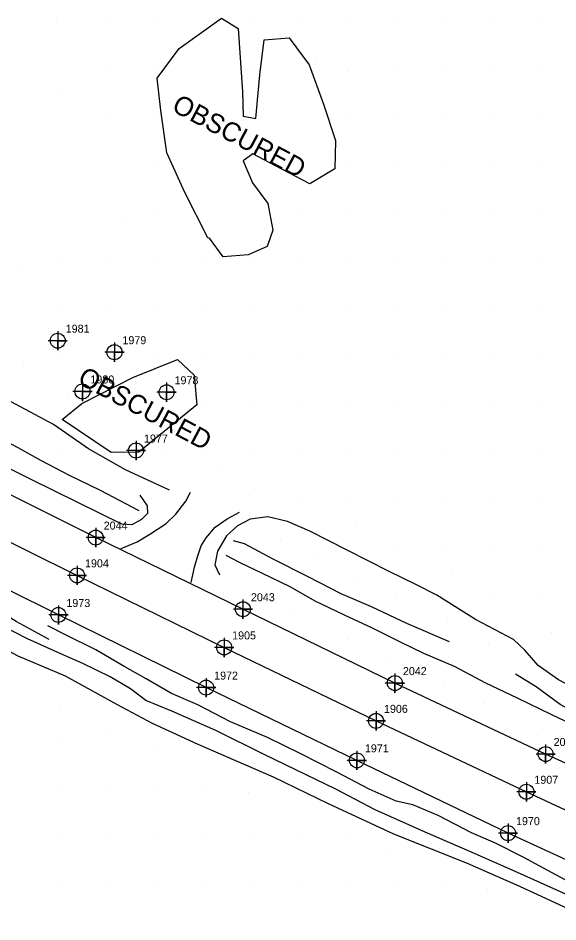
# Model space of a CAD drawing. Extents: x 1497074 to 1501343, y 481943 to 486114.
# Drawn here: x 1499522.1 to 1499690.7, y 482804.6 to 483087 of the extents above; entities that cross this region are included whole.
import ezdxf

# ---------------------------------------------------------------- set-up
doc = ezdxf.new("R2010")
doc.units = 0
for name, color, linetype in [('Exist DTM Crownline', 7, 'Continuous'), ('Exist DTM Crownline Cogo Number', 7, 'Continuous'), ('Exist DTM Crownline Cogo Point CELL', 7, 'Continuous'), ('Exist DTM Regular Point CELL', 7, 'Continuous'), ('Exist DTM Regular Point Cogo Number', 7, 'Continuous'), ('Exist Roads EOP', 7, 'Continuous'), ('Exist Roads EOP Cogo Number', 7, 'Continuous'), ('Exist Roads EOP Cogo Point CELL', 7, 'Continuous'), ('PH Exist DTM Breakline', 7, 'Continuous'), ('PH Exist DTM Obscure Area', 7, 'Continuous'), ('PH Exist DTM Obscure Area Text', 7, 'Continuous'), ('PH Exist DTM Point', 7, 'Continuous')]:
    doc.layers.add(name, color=color, linetype=linetype)

msp = doc.modelspace()

# ---------------------------------------------------------------- linework, layer by layer
at = {"layer": 'Exist DTM Crownline'}
msp.add_lwpolyline([(1499395.36, 482985.02), (1499443.87, 482960.81), (1499493.08, 482936.36), (1499540.5, 482912.88), (1499586.46, 482890.36), (1499633.9, 482867.4), (1499680.88, 482845.25), (1499726.12, 482824.18), (1499773.19, 482803.77), (1499819.04, 482785.34), (1499906.6, 482751.56), (1499930.69, 482742.84), (1499979.87, 482724.77), (1500026.26, 482708.17), (1500077.15, 482689.67), (1500127.52, 482671.55), (1500177.68, 482653.78), (1500231.5, 482634.52), (1500279.65, 482617.19), (1500328.73, 482599.71), (1500369.66, 482584.94)], dxfattribs=at)
at = {"layer": 'Exist DTM Crownline Cogo Point CELL'}
for points in [[(1499540.5, 482915.88), (1499540.5, 482909.88), (1499540.5, 482912.88), (1499543.5, 482912.88), (1499537.5, 482912.88)], [(1499586.46, 482893.36), (1499586.46, 482887.36), (1499586.46, 482890.36), (1499589.46, 482890.36), (1499583.46, 482890.36)], [(1499633.9, 482870.4), (1499633.9, 482864.4), (1499633.9, 482867.4), (1499636.9, 482867.4), (1499630.9, 482867.4)], [(1499680.88, 482848.25), (1499680.88, 482842.25), (1499680.88, 482845.25), (1499683.88, 482845.25), (1499677.88, 482845.25)]]:
    msp.add_lwpolyline(points, dxfattribs=at)
for centre in [(1499540.5, 482912.88), (1499586.46, 482890.36), (1499633.9, 482867.4), (1499680.88, 482845.25)]:
    msp.add_circle(centre, 2.34, dxfattribs=at)
at = {"layer": 'Exist DTM Regular Point CELL'}
for points in [[(1499534.46, 482989.2), (1499534.46, 482983.2), (1499534.46, 482986.2), (1499537.46, 482986.2), (1499531.46, 482986.2)], [(1499552.19, 482985.6), (1499552.19, 482979.6), (1499552.19, 482982.6), (1499555.19, 482982.6), (1499549.19, 482982.6)], [(1499542.19, 482973.34), (1499542.19, 482967.34), (1499542.19, 482970.34), (1499545.19, 482970.34), (1499539.19, 482970.34)], [(1499568.47, 482973.09), (1499568.47, 482967.09), (1499568.47, 482970.09), (1499571.47, 482970.09), (1499565.47, 482970.09)], [(1499558.92, 482954.88), (1499558.92, 482948.88), (1499558.92, 482951.88), (1499561.92, 482951.88), (1499555.92, 482951.88)]]:
    msp.add_lwpolyline(points, dxfattribs=at)
for centre in [(1499534.46, 482986.2), (1499552.19, 482982.6), (1499542.19, 482970.34), (1499568.47, 482970.09), (1499558.92, 482951.88)]:
    msp.add_circle(centre, 2.34, dxfattribs=at)
at = {"layer": 'Exist Roads EOP'}
for points in [[(1499731.6, 482836.87), (1499686.89, 482857.05), (1499639.8, 482879.21), (1499592.33, 482902.29), (1499546.33, 482924.68), (1499498.59, 482948.51), (1499459.31, 482968.94), (1499458.43, 482969.66), (1499428.27, 482984.38), (1499427.08, 482984.62), (1499402.41, 482996.96)], [(1499698.51, 482821.61), (1499675.14, 482832.32), (1499627.94, 482855.07), (1499580.83, 482877.79), (1499534.68, 482900.49), (1499486.84, 482924.26), (1499438.05, 482948.62), (1499388.86, 482973.08)]]:
    msp.add_lwpolyline(points, dxfattribs=at)
at = {"layer": 'Exist Roads EOP Cogo Point CELL'}
for points in [[(1499546.33, 482927.68), (1499546.33, 482921.68), (1499546.33, 482924.68), (1499549.33, 482924.68), (1499543.33, 482924.68)], [(1499592.33, 482905.29), (1499592.33, 482899.29), (1499592.33, 482902.29), (1499595.33, 482902.29), (1499589.33, 482902.29)], [(1499534.68, 482903.49), (1499534.68, 482897.49), (1499534.68, 482900.49), (1499537.68, 482900.49), (1499531.68, 482900.49)], [(1499639.8, 482882.21), (1499639.8, 482876.21), (1499639.8, 482879.21), (1499642.8, 482879.21), (1499636.8, 482879.21)], [(1499580.83, 482880.79), (1499580.83, 482874.79), (1499580.83, 482877.79), (1499583.83, 482877.79), (1499577.83, 482877.79)], [(1499686.89, 482860.05), (1499686.89, 482854.05), (1499686.89, 482857.05), (1499689.89, 482857.05), (1499683.89, 482857.05)], [(1499627.94, 482858.07), (1499627.94, 482852.07), (1499627.94, 482855.07), (1499630.94, 482855.07), (1499624.94, 482855.07)], [(1499675.14, 482835.32), (1499675.14, 482829.32), (1499675.14, 482832.32), (1499678.14, 482832.32), (1499672.14, 482832.32)]]:
    msp.add_lwpolyline(points, dxfattribs=at)
for centre in [(1499546.33, 482924.68), (1499592.33, 482902.29), (1499534.68, 482900.49), (1499639.8, 482879.21), (1499580.83, 482877.79), (1499686.89, 482857.05), (1499627.94, 482855.07), (1499675.14, 482832.32)]:
    msp.add_circle(centre, 2.34, dxfattribs=at)
at = {"layer": 'PH Exist DTM Breakline'}
for points in [[(1499569.38, 482939.45), (1499555.59, 482945.83), (1499544.06, 482952.45), (1499533.12, 482960.03), (1499519.92, 482967.05), (1499506.63, 482974.11), (1499495.82, 482979.85), (1499485.92, 482984.72), (1499476.91, 482989.41), (1499465.54, 482994.89)], [(1499554.47, 482928.86), (1499526.35, 482942.7), (1499499.25, 482956.26), (1499476.52, 482967.92), (1499464.94, 482974.18), (1499461.69, 482976.81), (1499460.19, 482979.45), (1499460.13, 482984.35), (1499460.87, 482990.61)], [(1499531.84, 482892.85), (1499521.45, 482898.49), (1499512.58, 482903.98), (1499499.86, 482910.46), (1499487.99, 482916.64), (1499479.25, 482921.85), (1499471.5, 482925.48), (1499460.32, 482930.95), (1499448.67, 482936.16), (1499435.81, 482941.98), (1499423.89, 482948.31), (1499412.5, 482953.79), (1499400.01, 482960.42), (1499390.51, 482965.44), (1499382.74, 482969.27), (1499372.58, 482974.7), (1499364.12, 482978.83), (1499355.7, 482982.98), (1499348.93, 482986.12)], [(1499559.95, 482933), (1499547.84, 482939.44), (1499538.16, 482944.09), (1499529.39, 482948.65), (1499522.08, 482952.68), (1499514.27, 482956.74), (1499507.24, 482960.1), (1499499.29, 482963.79), (1499490.71, 482967.25), (1499483.35, 482970.57), (1499475.46, 482974.49), (1499462.75, 482980.59)], [(1499339.96, 482972.14), (1499355.23, 482965.11), (1499369.9, 482958.45), (1499380.09, 482953.58), (1499393.87, 482947.39), (1499408.71, 482939.89), (1499424.74, 482932.88), (1499443.1, 482924.02), (1499461.53, 482915.83), (1499479.74, 482907.55), (1499491.77, 482902.64), (1499508.84, 482894.62), (1499522.01, 482887.72), (1499536.81, 482881.48), (1499553, 482872.55), (1499563.99, 482866.65), (1499578.21, 482860.08), (1499601.81, 482849.91), (1499618.96, 482841.56), (1499639.41, 482832.09), (1499662.39, 482822.9), (1499678.74, 482815.76), (1499696.7, 482807.4)], [(1499554.26, 482921.29), (1499559.29, 482923.4), (1499563.27, 482925.75), (1499568.35, 482929.05), (1499571.36, 482931.96), (1499574.49, 482936.07), (1499575.98, 482938.87)], [(1499560.15, 482937.92), (1499562.37, 482934.58), (1499562.51, 482932.17), (1499560.66, 482930.28), (1499557.63, 482928.61), (1499554.47, 482928.86)], [(1499576.18, 482910.69), (1499577.24, 482915.48), (1499578.1, 482918.67), (1499579.3, 482922.15), (1499580.87, 482924.6), (1499583.68, 482927.89), (1499587.37, 482930.55), (1499591.29, 482932.58)], [(1499728.17, 482864.71), (1499702.51, 482874.12), (1499690.89, 482880.26), (1499684.61, 482884.66), (1499680.37, 482889.51), (1499676.82, 482892.78), (1499664.97, 482899.08), (1499652.87, 482906.64), (1499646.32, 482910), (1499638.05, 482914.09), (1499624.86, 482920.72), (1499613.26, 482926.65), (1499606.22, 482929.74), (1499600.1, 482931.21), (1499594.56, 482930.46), (1499590.64, 482928.3), (1499587.22, 482925.25), (1499584.34, 482920.44), (1499583.55, 482916.2), (1499585.04, 482913.08)], [(1499656.9, 482892.08), (1499643.49, 482897.82), (1499632.54, 482903.01), (1499623.02, 482907.09), (1499612.74, 482912.46), (1499601.74, 482917.93), (1499592.77, 482922.7), (1499589.4, 482923.64)], [(1499721.91, 482853.6), (1499699.59, 482864.2), (1499688.86, 482869.27), (1499678.12, 482874.52), (1499668.21, 482879.23), (1499658.43, 482884.43), (1499648.88, 482888.44), (1499641.59, 482891.96), (1499632.8, 482896.4), (1499624.08, 482900.44), (1499614.89, 482904.83), (1499607.06, 482909.25), (1499598.49, 482913.47), (1499591.5, 482916.76), (1499587.07, 482919.11)], [(1499699.65, 482810.33), (1499678.1, 482820.01), (1499663.95, 482826.25), (1499649.3, 482832.61), (1499633.61, 482839.58), (1499621.33, 482846.11), (1499612.12, 482850.55), (1499599.21, 482856.79), (1499583.86, 482864.38), (1499570.07, 482870.46), (1499562, 482873.73), (1499557.2, 482877.4), (1499550.82, 482881.15), (1499542.26, 482885.28), (1499535.39, 482888.37), (1499525.07, 482893.07), (1499516.9, 482897.23)], [(1499699.6, 482814.15), (1499688.98, 482819.88), (1499679.9, 482824.77), (1499671.18, 482829.14), (1499663.77, 482832.4), (1499653.33, 482837.81), (1499645.42, 482841.12), (1499640.24, 482842.29), (1499631.76, 482846.06), (1499621.67, 482851.42), (1499610.2, 482857.24), (1499599.95, 482862.19), (1499588.42, 482867.15), (1499578.23, 482872.38), (1499569.99, 482875.99), (1499562.05, 482880.55), (1499555.43, 482884.32), (1499546.41, 482889.61), (1499536.92, 482894.32), (1499531.39, 482897.13)], [(1499724.06, 482857.01), (1499711.38, 482861.87), (1499699.91, 482867.97), (1499691.43, 482872.47), (1499683.93, 482878), (1499677.5, 482881.99)]]:
    msp.add_lwpolyline(points, dxfattribs=at)
at = {"layer": 'PH Exist DTM Obscure Area'}
for points in [[(1499581.36, 483018.37), (1499574.18, 483032.55), (1499568.51, 483044.88), (1499566.66, 483058.15), (1499565.56, 483068.22), (1499572.37, 483077.51), (1499585.6, 483087.01), (1499590.88, 483083.76), (1499592.2, 483064), (1499592.37, 483056.41), (1499596.35, 483055.65)], [(1499596.35, 483055.65), (1499597.56, 483069.23), (1499598.94, 483080.26), (1499606.82, 483080.87), (1499612.97, 483072.4), (1499617.45, 483060.14), (1499621.22, 483048.79)], [(1499621.22, 483048.79), (1499621.04, 483039.95), (1499613.23, 483035.25), (1499602.49, 483040.81), (1499595.43, 483044.56), (1499592.41, 483042.38), (1499595.29, 483035.57), (1499600.11, 483029.04), (1499601.62, 483020.71), (1499599.88, 483015.59), (1499593.99, 483013.06), (1499586.17, 483012.44), (1499581.89, 483018.27)], [(1499581.89, 483018.27), (1499581.36, 483018.37)], [(1499577.9, 482966.2), (1499559.77, 482951.39), (1499551.2, 482951.25), (1499535.81, 482961.56), (1499541.99, 482966.6), (1499557.89, 482974.75), (1499571.9, 482980.35), (1499577.1, 482975.43)], [(1499577.1, 482975.43), (1499577.9, 482966.2)]]:
    msp.add_lwpolyline(points, dxfattribs=at)
at = {"layer": 'PH Exist DTM Point'}
for p, q in [((1499534.2, 483086.82), (1499534.2, 483086.82)), ((1499549.29, 483086.76), (1499549.29, 483086.76)), ((1499564.29, 483086.76), (1499564.29, 483086.76)), ((1499594.29, 483086.76), (1499594.29, 483086.76)), ((1499609.29, 483086.76), (1499609.29, 483086.76)), ((1499624.29, 483086.76), (1499624.29, 483086.76)), ((1499639.29, 483086.76), (1499639.29, 483086.76)), ((1499654.29, 483086.76), (1499654.29, 483086.76)), ((1499669.29, 483086.76), (1499669.29, 483086.76)), ((1499684.29, 483086.76), (1499684.29, 483086.76)), ((1499615.04, 483073.51), (1499615.04, 483073.51)), ((1499549.29, 483071.76), (1499549.29, 483071.76)), ((1499564.29, 483071.76), (1499564.29, 483071.76)), ((1499594.29, 483071.76), (1499594.29, 483071.76)), ((1499639.29, 483071.76), (1499639.29, 483071.76)), ((1499654.29, 483071.76), (1499654.29, 483071.76)), ((1499669.29, 483071.76), (1499669.29, 483071.76)), ((1499684.29, 483071.76), (1499684.29, 483071.76)), ((1499625.41, 483070.18), (1499625.41, 483070.18)), ((1499535.94, 483063.93), (1499535.94, 483063.93)), ((1499549.29, 483056.76), (1499549.29, 483056.76)), ((1499564.29, 483056.76), (1499564.29, 483056.76)), ((1499594.29, 483056.76), (1499594.29, 483056.76)), ((1499624.29, 483056.76), (1499624.29, 483056.76)), ((1499639.29, 483056.76), (1499639.29, 483056.76)), ((1499654.29, 483056.76), (1499654.29, 483056.76)), ((1499669.29, 483056.76), (1499669.29, 483056.76)), ((1499684.29, 483056.76), (1499684.29, 483056.76)), ((1499564.29, 483041.76), (1499564.29, 483041.76)), ((1499596.08, 483041.54), (1499596.08, 483041.54)), ((1499624.29, 483041.76), (1499624.29, 483041.76)), ((1499639.29, 483041.76), (1499639.29, 483041.76)), ((1499654.29, 483041.76), (1499654.29, 483041.76)), ((1499669.29, 483041.76), (1499669.29, 483041.76)), ((1499684.29, 483041.76), (1499684.29, 483041.76)), ((1499564.29, 483026.76), (1499564.29, 483026.76)), ((1499609.29, 483026.76), (1499609.29, 483026.76)), ((1499624.29, 483026.76), (1499624.29, 483026.76)), ((1499639.29, 483026.76), (1499639.29, 483026.76)), ((1499654.29, 483026.76), (1499654.29, 483026.76)), ((1499669.29, 483026.76), (1499669.29, 483026.76)), ((1499684.29, 483026.76), (1499684.29, 483026.76)), ((1499554.84, 483023.81), (1499554.84, 483023.81)), ((1499577.14, 483022.72), (1499577.14, 483022.72)), ((1499564.29, 483011.76), (1499564.29, 483011.76)), ((1499579.29, 483011.76), (1499579.29, 483011.76)), ((1499594.29, 483011.76), (1499594.29, 483011.76)), ((1499609.29, 483011.76), (1499609.29, 483011.76)), ((1499624.29, 483011.76), (1499624.29, 483011.76)), ((1499639.29, 483011.76), (1499639.29, 483011.76)), ((1499654.29, 483011.76), (1499654.29, 483011.76)), ((1499669.29, 483011.76), (1499669.29, 483011.76)), ((1499684.29, 483011.76), (1499684.29, 483011.76)), ((1499522.26, 483009.05), (1499522.26, 483009.05)), ((1499535.67, 483011.02), (1499535.67, 483011.02)), ((1499550.55, 483011.09), (1499550.55, 483011.09)), ((1499534.29, 482996.76), (1499534.29, 482996.76)), ((1499549.29, 482996.76), (1499549.29, 482996.76)), ((1499564.29, 482996.76), (1499564.29, 482996.76)), ((1499579.29, 482996.76), (1499579.29, 482996.76)), ((1499594.29, 482996.76), (1499594.29, 482996.76)), ((1499609.29, 482996.76), (1499609.29, 482996.76)), ((1499624.29, 482996.76), (1499624.29, 482996.76)), ((1499639.29, 482996.76), (1499639.29, 482996.76)), ((1499654.29, 482996.76), (1499654.29, 482996.76)), ((1499669.29, 482996.76), (1499669.29, 482996.76)), ((1499684.29, 482996.76), (1499684.29, 482996.76)), ((1499534.29, 482981.76), (1499534.29, 482981.76)), ((1499549.29, 482981.76), (1499549.29, 482981.76)), ((1499564.29, 482981.76), (1499564.29, 482981.76)), ((1499579.29, 482981.76), (1499579.29, 482981.76)), ((1499594.29, 482981.76), (1499594.29, 482981.76)), ((1499609.29, 482981.76), (1499609.29, 482981.76)), ((1499624.29, 482981.76), (1499624.29, 482981.76)), ((1499639.29, 482981.76), (1499639.29, 482981.76)), ((1499654.29, 482981.76), (1499654.29, 482981.76)), ((1499669.29, 482981.76), (1499669.29, 482981.76)), ((1499684.29, 482981.76), (1499684.29, 482981.76)), ((1499523.83, 482978.38), (1499523.83, 482978.38)), ((1499549.74, 482972.23), (1499549.74, 482972.23)), ((1499537.4, 482969.36), (1499537.4, 482969.36)), ((1499579.29, 482966.76), (1499579.29, 482966.76)), ((1499594.29, 482966.76), (1499594.29, 482966.76)), ((1499609.29, 482966.76), (1499609.29, 482966.76)), ((1499624.29, 482966.76), (1499624.29, 482966.76)), ((1499639.29, 482966.76), (1499639.29, 482966.76)), ((1499654.29, 482966.76), (1499654.29, 482966.76)), ((1499669.29, 482966.76), (1499669.29, 482966.76)), ((1499684.29, 482966.76), (1499684.29, 482966.76)), ((1499534.65, 482952.45), (1499534.65, 482952.45)), ((1499568.23, 482950.54), (1499568.23, 482950.54)), ((1499579.29, 482951.76), (1499579.29, 482951.76)), ((1499594.29, 482951.76), (1499594.29, 482951.76)), ((1499609.29, 482951.76), (1499609.29, 482951.76)), ((1499624.29, 482951.76), (1499624.29, 482951.76)), ((1499639.29, 482951.76), (1499639.29, 482951.76)), ((1499654.29, 482951.76), (1499654.29, 482951.76)), ((1499669.29, 482951.76), (1499669.29, 482951.76)), ((1499684.29, 482951.76), (1499684.29, 482951.76)), ((1499584.42, 482946.11), (1499584.42, 482946.11)), ((1499595.94, 482939.95), (1499595.94, 482939.95)), ((1499609.29, 482936.77), (1499609.29, 482936.77)), ((1499624.29, 482936.76), (1499624.29, 482936.76)), ((1499639.29, 482936.76), (1499639.29, 482936.76)), ((1499654.29, 482936.76), (1499654.29, 482936.76)), ((1499669.29, 482936.76), (1499669.29, 482936.76)), ((1499684.29, 482936.76), (1499684.29, 482936.76)), ((1499627.69, 482928.17), (1499627.69, 482928.17)), ((1499604.08, 482923.72), (1499604.08, 482923.72)), ((1499639.29, 482921.76), (1499639.29, 482921.76)), ((1499654.29, 482921.76), (1499654.29, 482921.76)), ((1499669.29, 482921.76), (1499669.29, 482921.76)), ((1499684.29, 482921.76), (1499684.29, 482921.76)), ((1499615.88, 482918.26), (1499615.88, 482918.26)), ((1499657.92, 482913.59), (1499657.92, 482913.59)), ((1499628.08, 482912.03), (1499628.08, 482912.03)), ((1499594.37, 482906.92), (1499594.37, 482906.92)), ((1499640.25, 482906.25), (1499640.25, 482906.25)), ((1499669.29, 482906.76), (1499669.29, 482906.76)), ((1499684.29, 482906.76), (1499684.29, 482906.76)), ((1499606.83, 482902.1), (1499606.83, 482902.1)), ((1499656.18, 482898.59), (1499656.18, 482898.59)), ((1499624.87, 482892.86), (1499624.87, 482892.86)), ((1499688.79, 482894.96), (1499688.79, 482894.96)), ((1499668.97, 482891.17), (1499668.97, 482891.17)), ((1499638.55, 482886.7), (1499638.55, 482886.7)), ((1499655.31, 482878.7), (1499655.31, 482878.7)), ((1499534.99, 482872.36), (1499534.99, 482872.36)), ((1499667.9, 482872.92), (1499667.9, 482872.92)), ((1499685.96, 482864.9), (1499685.96, 482864.9)), ((1499534.29, 482861.76), (1499534.29, 482861.76)), ((1499549.8, 482862.74), (1499549.8, 482862.74)), ((1499564.5, 482858.33), (1499564.5, 482858.33)), ((1499534.29, 482846.76), (1499534.29, 482846.76)), ((1499549.29, 482846.76), (1499549.29, 482846.76)), ((1499564.29, 482846.76), (1499564.29, 482846.76)), ((1499579.29, 482846.76), (1499579.29, 482846.76)), ((1499594.09, 482845.1), (1499594.09, 482845.1)), ((1499534.29, 482831.76), (1499534.29, 482831.76)), ((1499549.29, 482831.76), (1499549.29, 482831.76)), ((1499564.29, 482831.76), (1499564.29, 482831.76)), ((1499579.29, 482831.76), (1499579.29, 482831.76)), ((1499594.29, 482831.76), (1499594.29, 482831.76)), ((1499609.29, 482831.76), (1499609.29, 482831.76)), ((1499624.29, 482831.76), (1499624.29, 482831.76)), ((1499638.01, 482827.43), (1499638.01, 482827.43)), ((1499534.29, 482816.76), (1499534.29, 482816.76)), ((1499549.29, 482816.76), (1499549.29, 482816.76)), ((1499564.29, 482816.76), (1499564.29, 482816.76)), ((1499579.29, 482816.76), (1499579.29, 482816.76)), ((1499594.29, 482816.76), (1499594.29, 482816.76)), ((1499609.29, 482816.76), (1499609.29, 482816.76)), ((1499624.29, 482816.76), (1499624.29, 482816.76)), ((1499639.29, 482816.76), (1499639.29, 482816.76)), ((1499654.29, 482816.76), (1499654.29, 482816.76)), ((1499668.58, 482814.7), (1499668.58, 482814.7))]:
    msp.add_line(p, q, dxfattribs=at)

# ---------------------------------------------------------------- texts
at = {"layer": 'Exist DTM Crownline Cogo Number'}
for s, p in [('1904', (1499543, 482915.38)), ('1905', (1499588.96, 482892.86)), ('1906', (1499636.4, 482869.91)), ('1907', (1499683.38, 482847.75))]:
    msp.add_text(s, height=2.5, dxfattribs=at).set_placement(p)
at = {"layer": 'Exist DTM Regular Point Cogo Number'}
for s, p in [('1981', (1499536.96, 482988.7)), ('1979', (1499554.69, 482985.11)), ('1980', (1499544.69, 482972.84)), ('1978', (1499570.97, 482972.59)), ('1977', (1499561.42, 482954.38))]:
    msp.add_text(s, height=2.5, dxfattribs=at).set_placement(p)
at = {"layer": 'Exist Roads EOP Cogo Number'}
for s, p in [('2044', (1499548.83, 482927.18)), ('2043', (1499594.83, 482904.79)), ('1973', (1499537.18, 482902.99)), ('1972', (1499583.33, 482880.29)), ('2042', (1499642.3, 482881.71)), ('2041', (1499689.39, 482859.55)), ('1971', (1499630.44, 482857.57)), ('1970', (1499677.64, 482834.82))]:
    msp.add_text(s, height=2.5, dxfattribs=at).set_placement(p)
at = {"layer": 'PH Exist DTM Obscure Area Text'}
for p in [(1499569.74, 483058.18), (1499540.32, 482973.06)]:
    msp.add_text('OBSCURED', height=6, rotation=332.0096, dxfattribs=at).set_placement(p)

doc.saveas('drawing.dxf')
